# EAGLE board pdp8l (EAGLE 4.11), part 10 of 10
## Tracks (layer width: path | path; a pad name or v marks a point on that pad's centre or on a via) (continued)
VCC  (via drill 0.61) (continued)
  Bottom 0.508: 358.44,271.73 349.1,271.73 348.29,272.54 A09.A2 347.07,272.95 345.85,272.95 344.22,274.57 336.91,274.57 335.69,273.36 A10.A2 334.47,272.54 333.65,271.73 323.49,271.73 322.68,272.54 A11.A2 321.46,272.95 320.65,272.14 317.4,272.14 316.99,271.73 307.64,271.73 | 358.44,271.73 359.66,272.95 A08.A2 | 358.44,271.73 371.04,271.73 372.26,272.95 AB07.AA2 373.48,273.76 374.29,274.57 387.71,274.57 | 387.71,274.57 386.49,273.36 AB06.AA2 | 387.71,274.57 396.65,274.57 | 396.65,274.57 397.87,273.36 AB05.AA2 | 409.25,274.57 410.46,273.36 AB04.AA2 | 396.65,274.57 409.25,274.57 | 421.84,274.57 423.06,273.36 AB03.AA2 | 409.25,274.57 421.84,274.57 | 434.85,274.57 436.07,273.36 AB02.AA2 | 421.84,274.57 434.85,274.57 | 434.85,274.57 447.45,274.57 448.67,273.36 A01.A2 | 15.44,271.73 6.1,271.73 5.28,272.54 A36.A2 | 15.44,271.73 16.66,272.95 A35.A2 | 28.85,271.73 29.67,272.54 A34.A2 | 28.85,271.73 15.44,271.73 | 28.85,271.73 41.45,271.73 42.27,272.54 A33.A2 | A32.A2 56.08,272.54 56.9,271.73 66.24,271.73 67.46,272.95 AB31.AA2 68.68,272.54 69.09,272.14 73.15,272.14 73.56,271.73 75.59,271.73 76.4,272.54 80.47,272.54 AB30.AA2 81.69,272.95 82.5,272.14 86.16,272.14 86.56,271.73 92.25,271.73 93.07,272.54 AB29.AA2 94.28,272.95 97.94,272.95 99.16,271.73 100.79,271.73 101.6,272.54 105.26,272.54 105.66,272.95 A28A.A2 | A24.A2 157.68,272.54 161.75,272.54 162.56,271.73 165.81,271.73 167.03,272.95 169.06,272.95 A23.A2 170.28,273.76 171.09,274.57 209.7,274.57 | 209.7,274.57 208.48,273.36 A20.A2 | 209.7,274.57 218.64,274.57 219.86,273.36 A19.A2 221.08,272.54 221.49,272.14 225.55,272.14 225.96,271.73 231.24,271.73 232.05,272.54 232.87,272.54 A18.A2 234.09,273.36 235.31,274.57 244.25,274.57 245.47,273.36 A17.A2 246.69,272.54 247.5,271.73 256.85,271.73
  Bottom 0.508: 256.85,271.73 258.06,272.95 A16.A2 | 269.44,271.73 270.66,272.95 A15.A2 | 256.85,271.73 269.44,271.73 | 282.85,271.73 283.67,272.54 A14.A2 | 269.44,271.73 282.85,271.73 | 295.45,271.73 296.27,272.54 A13.A2 | 282.85,271.73 295.45,271.73 | 307.64,271.73 308.86,272.95 A12.A2 | 295.45,271.73 307.64,271.73 | D01.A2 448.67,66.5 447.45,65.28 442.16,65.28 440.94,66.5 437.29,66.5 D02.A2 436.07,66.09 435.25,65.28 425.09,65.28 424.28,66.09 CD03.BA2 423.06,66.5 419.81,66.5 418.59,65.28 413.71,65.28 412.5,66.5 411.68,66.5 D04.A2 410.46,66.5 406.81,66.5 405.59,65.28 400.3,65.28 399.08,66.5 D05.A2 397.87,66.9 396.24,66.9 395.02,68.12 387.71,68.12 386.49,66.9 D06.A2 385.27,66.09 382.02,66.09 381.2,65.28 378.36,65.28 377.95,65.68 373.89,65.68 373.48,66.09 D07.A2 372.26,66.5 369.82,66.5 368.61,65.28 365.76,65.28 365.35,65.68 361.29,65.68 360.88,66.09 D08.A2 359.66,66.5 358.85,65.68 355.19,65.68 354.79,65.28 352.75,65.28 351.54,66.5 348.29,66.5 D09.A2 347.07,66.5 345.85,65.28 336.91,65.28 335.69,66.5 D10.A2 334.47,66.09 334.06,65.68 330,65.68 329.59,65.28 320.24,65.28 | 53.65,68.12 44.7,68.12 43.48,66.9 D33.A2 | 53.65,68.12 54.86,66.9 D32.A2 | 66.24,68.12 67.46,66.9 D31.A2 | 66.24,68.12 53.65,68.12 | 79.65,68.12 80.47,67.31 D30.A2 | 79.65,68.12 66.24,68.12 | 89,67.31 88.19,68.12 79.65,68.12 | 89,67.31 89.41,66.9 93.07,66.9 D29.A2 | 99.57,69.34 102.41,66.5 105.66,66.5 D28.A2 | 99.57,69.34 91.03,69.34 89,67.31 | 99.57,69.34 v115.82,69.34 116.23,69.34 v145.09,69.34 | 155.25,65.28 149.96,65.28 149.15,66.09 145.49,66.09 145.09,66.5 D25.A2 | 155.25,65.28 156.46,66.5 D24.A2
  Bottom 0.508: 155.25,65.28 167.84,65.28 169.06,66.5 D23.A2 170.28,67.31 171.09,68.12 217.83,68.12 219.05,66.9 219.86,66.9 D19.A2 221.08,67.31 221.89,68.12 232.05,68.12 232.87,67.31 D18.A2 234.09,66.5 234.49,66.09 238.15,66.09 238.96,65.28 240.59,65.28 241.81,66.5 245.47,66.5 D17.A2 246.69,66.5 247.5,65.68 251.16,65.68 251.56,65.28 256.85,65.28 | 256.85,65.28 258.06,66.5 D16.A2 | 269.44,65.28 270.66,66.5 D15.A2 | 256.85,65.28 269.44,65.28 | 282.85,65.28 283.67,66.09 D14.A2 | 269.44,65.28 282.85,65.28 | 295.05,65.28 296.27,66.5 D13.A2 | 282.85,65.28 295.05,65.28 | 307.64,65.28 308.86,66.5 D12.A2 | 295.05,65.28 307.64,65.28 | 320.24,65.28 321.46,66.5 D11.A2 | 307.64,65.28 320.24,65.28 | 53.65,135.18 44.3,135.18 43.48,135.99 C33.A2 | 53.65,135.18 54.86,136.4 C32.A2 | 66.24,135.18 67.46,136.4 C31.A2 | 53.65,135.18 66.24,135.18 | 79.65,135.18 80.47,135.99 C30.A2 | 66.24,135.18 79.65,135.18 | 92.25,135.18 93.07,135.99 C29.A2 | 79.65,135.18 92.25,135.18 | 92.25,135.18 104.44,135.18 105.66,136.4 C28.A2 106.88,136.8 108.1,138.02 117.04,138.02 | 117.04,138.02 118.26,136.8 C27.A2 | 130.05,138.02 131.27,136.8 C26.A2 | 117.04,138.02 130.05,138.02 | 142.65,138.02 143.87,136.8 C25.A2 | 130.05,138.02 142.65,138.02 | 155.25,138.02 156.46,136.8 C24.A2 | 142.65,138.02 155.25,138.02 | 155.25,138.02 167.84,138.02 169.06,136.8 C23.A2 170.28,137.21 171.09,138.02 221.89,138.02 | 221.89,138.02 222.3,138.43 231.24,138.43 232.87,136.8 C18.A2 234.09,136.8 235.31,138.02 244.25,138.02 245.47,136.8 C17.A2 246.69,135.99 247.5,135.18 256.85,135.18 258.06,136.4 C16.A2 259.28,135.99 260.1,135.18 269.44,135.18 270.66,136.4 C15.A2 271.88,135.99 272.69,135.18 278.79,135.18 279.2,135.59 283.26,135.59 283.67,135.99 C14.A2 284.89,136.4 285.7,135.59 289.36,135.59 289.76,135.18 291.39,135.18 292.61,136.4 296.27,136.4 C13.A2 297.49,135.99 298.3,135.18 303.99,135.18 305.21,136.4 308.86,136.4 C12.A2 310.08,135.99 310.49,135.59 314.55,135.59 314.96,135.18 316.99,135.18 318.21,136.4 321.46,136.4 C11.A2 322.68,135.99 323.49,135.18 333.65,135.18 334.47,135.99 C10.A2 335.69,136.4 337.31,136.4 338.53,135.18 342.19,135.18 342.6,135.59 346.66,135.59 347.07,135.99 C09.A2 348.29,135.99 348.69,135.59 352.75,135.59 353.16,135.18 356.01,135.18 357.23,136.4 359.66,136.4 C08.A2 360.88,135.99 361.29,135.59 365.35,135.59 365.76,135.18 368.2,135.18 369.42,136.4 372.26,136.4 C07.A2 373.48,135.99 374.29,135.18 387.71,135.18
  Bottom 0.508: 221.89,138.02 221.08,137.21 C19.A2 | 435.25,135.18 425.09,135.18 424.28,135.99 CD03.AA2 423.06,136.4 419.81,136.4 418.19,138.02 412.9,138.02 411.68,136.8 C04.A2 410.46,136.4 409.25,135.18 397.05,135.18 | 435.25,135.18 436.07,135.99 C02.A2 | 435.25,135.18 447.85,135.18 448.67,135.99 C01.A2 | 387.71,135.18 386.49,136.4 C06.A2 | 387.71,135.18 397.05,135.18 | 397.05,135.18 397.87,135.99 C05.A2 | 295.45,201.83 286.11,201.83 284.89,203.05 B14.A2 283.67,202.64 279.6,202.64 278.79,201.83 269.44,201.83 | 295.45,201.83 296.27,202.64 B13.A2 | 307.64,201.83 308.86,203.05 B12.A2 | 307.64,201.83 295.45,201.83 | 320.24,201.83 321.46,203.05 B11.A2 | 320.24,201.83 307.64,201.83 | 332.44,201.83 320.24,201.83 | 332.44,201.83 333.65,201.83 334.47,202.64 B10.A2 335.69,203.05 338.12,203.05 339.34,201.83 346.25,201.83 347.07,202.64 B09.A2 348.29,203.05 349.5,201.83 355.19,201.83 356.01,202.64 360.07,202.64 B08.A2 360.88,203.45 362.1,204.67 371.04,204.67 372.26,203.45 AB07.BA2 373.48,202.64 374.29,201.83 387.71,201.83 | 387.71,201.83 386.49,203.05 AB06.BA2 | 387.71,201.83 392.99,201.83 393.8,202.64 397.87,202.64 AB05.BA2 399.08,203.05 399.9,202.23 403.56,202.23 403.96,201.83 412.5,201.83 | 412.5,201.83 411.68,202.64 AB04.BA2 | 412.5,201.83 421.84,201.83 | 421.84,201.83 423.06,203.05 AB03.BA2 | 435.25,201.83 436.07,202.64 AB02.BA2 | 421.84,201.83 435.25,201.83 | 435.25,201.83 447.85,201.83 448.67,202.64 B01.A2 | B33.A2 43.48,203.05 44.7,201.83 53.65,201.83 54.86,203.05 B32.A2 56.08,202.64 56.9,201.83 66.24,201.83 | 66.24,201.83 67.46,203.05 AB31.BA2 | 66.24,201.83 79.65,201.83 80.47,202.64 AB30.BA2 81.69,203.45 84.94,203.45 86.16,204.67 91.85,204.67 93.07,203.45 AB29.BA2 94.28,203.45 95.5,204.67 104.44,204.67 105.66,203.45 B28.A2 106.88,203.45 108.1,204.67 155.25,204.67 156.46,203.45 B24.A2 157.68,202.64 158.5,201.83 167.84,201.83 169.06,203.05 B23.A2 170.28,203.86 171.09,204.67 209.7,204.67
  Bottom 0.508: 209.7,204.67 208.48,203.45 B20.A2 | 218.64,204.67 209.7,204.67 | 218.64,204.67 219.86,203.45 B19.A2 | 218.64,204.67 232.05,204.67 232.87,203.86 B18.A2 234.09,203.05 235.31,201.83 244.65,201.83 | 244.65,201.83 245.47,202.64 B17.A2 | 256.85,201.83 258.06,203.05 B16.A2 | 256.85,201.83 244.65,201.83 | 269.44,201.83 270.66,203.05 B15.A2 | 269.44,201.83 256.85,201.83 | v332.44,203.05 332.44,201.83
WC_OVERFLOW\  (via drill 0.61)
  Route2 0.203: v304.39,14.07 334.47,44.15 334.47,46.99 D10.H2
  Route15 0.203: v209.7,8.79 209.7,22.61 164.19,68.12 160.53,68.12 156.06,72.59 156.06,76.25 123.14,109.17 120.7,109.17 119.48,110.39 C27.K2
  Bottom 0.203: v304.39,14.07 301.14,10.82 232.05,10.82 230.02,8.79 v209.7,8.79
WC_SET\  (via drill 0.61)
  Top 0.203: 308.05,20.98 308.86,21.79 D12.S2 | 307.64,20.57 308.05,20.98 | 307.64,20.57 306.83,19.76 D12.T2 | v145.09,6.76 130.05,21.79 130.05,87.63 129.24,88.44 C26.T2 | v305.61,9.6 307.64,11.63 307.64,20.57 | 308.05,20.98 308.05,33.17 309.27,34.39 D12.M2
  Bottom 0.203: v145.09,6.76 145.49,6.35 181.66,6.35 182.07,5.94 212.14,5.94 212.55,6.35 245.87,6.35 246.69,7.16 261.31,7.16 262.94,5.54 291.39,5.54 292.61,6.76 302.77,6.76 v305.61,9.6 | D11.M2 321.46,34.8 320.24,33.58 310.9,33.58 310.08,34.39 D12.M2
WORD_COUNT
  Bottom 0.203: D10.P2 335.69,28.3 340.56,28.3 D10.P1
WORD_COUNT\  (via drill 0.61)
  Top 0.203: v421.84,40.89 421.84,28.3 417.78,24.23 417.78,23.01 D04.S1 | D11.H1 328.78,46.99 330,45.77 330,34.39 329.59,33.98 329.59,32.36 330.4,31.55 330.4,26.67 331.22,25.86 D10.R2 332.03,24.64 333.25,23.42 333.25,12.04 332.44,11.23 327.15,11.23 327.15,14.07 317.4,23.83 | 310.9,16.51 314.55,16.51 314.55,18.95 317.4,21.79 317.4,23.83 | 310.9,16.51 310.08,16.51 D12.U2 | 317.4,23.83 317.4,33.17 316.18,34.39 D12.M1 | v134.11,77.47 130.45,81.13 130.45,118.92 129.24,120.14 C26.F2 | v304.8,70.16 304.8,43.33 310.9,37.24 310.9,16.51 | v305.61,230.28 304.8,229.46 304.8,207.92 305.61,207.11 305.61,201.42 305.21,201.02 v305.21,189.23 | v298.3,189.23 v298.3,146.96 | v288.14,146.96 288.14,134.77 288.54,134.37 v288.54,75.84
  Bottom 0.203: D02.S2 436.07,21.79 435.25,20.98 419,20.98 418.19,21.79 D04.S1 416.97,22.61 416.15,23.42 341.78,23.42 338.53,26.67 333.25,26.67 332.44,25.86 D10.R2 | v421.84,40.89 423.47,42.52 434.04,42.52 434.44,42.93 444.19,42.93 445.41,44.15 D01.J2 | v134.11,77.47 141.43,70.16 176.78,70.16 177.19,69.75 288.54,69.75 288.95,70.16 | 288.95,70.16 v304.8,70.16 | v305.61,230.28 317.81,230.28 318.62,231.09 A11.R2 | v305.21,189.23 v298.3,189.23 | v298.3,146.96 v288.14,146.96 | v288.54,75.84 288.54,70.16 288.95,70.16
WRITE  (via drill 0.61)
  Top 0.203: C25.L1 147.52,108.76 146.3,109.98 146.3,125.02 147.52,126.24 C25.D1 | 143.05,36.83 144.27,35.61 D25.M2 | 143.05,36.83 v143.05,55.52 | v260.1,14.88 260.1,20.98 259.28,21.79 D16.S2 | v141.83,14.48 143.05,15.7 143.05,27.89 | 143.05,27.89 143.05,36.83 | v138.99,109.58 136.96,107.54 136.96,33.98 143.05,27.89
  Bottom 0.203: D16.S2 259.28,21.79 264.57,21.79 D16.S1 | v143.05,55.52 141.83,56.74 D25.D2 | v260.1,14.88 259.69,14.48 v141.83,14.48 | v138.99,109.58 145.9,109.58 147.12,108.36 C25.L1
X_R/W_RETURN  (via drill 0.61)
  Top 0.203: v152.4,165.66 152.81,165.25 152.81,52.68 v153.21,52.27 152.81,52.27 152.81,49.84 155.65,46.99 155.65,21.79 v158.09,19.36 | v149.56,50.24 149.56,42.52 150.37,41.71 D25.K1
  Route15 0.203: v152.4,165.66 128.83,189.23 128.83,192.89 B26.D2
  Bottom 0.203: D18.T2 229.62,18.54 228.8,17.73 219.46,17.73 218.24,18.95 D19.T2 217.02,18.54 216.21,17.73 159.72,17.73 v158.09,19.36 | 149.56,52.27 143.05,52.27 141.83,51.05 D25.F2 | v153.21,52.27 149.56,52.27 | 149.56,52.27 v149.56,50.24
X_R/W_SOURCE  (via drill 0.61)
  Top 0.203: v150.77,115.67 150.77,111.61 C25.K1 | A26.D2 129.24,263.2 133.71,263.2 133.71,203.45 136.14,201.02 136.14,128.27 141.02,123.39 141.02,121.36 C25.F2 | v155.65,110.39 155.25,109.98 155.25,90.88 154.03,89.66 C24.T2
  Bottom 0.203: C24.T2 154.43,88.44 154.84,88.04 159.31,88.04 159.72,87.63 163.78,87.63 164.59,88.44 166.22,88.44 C23.T2 | v150.77,115.67 141.83,115.67 141.83,120.14 C25.F2 | v155.65,110.39 155.25,110.79 151.59,110.79 C25.K1
Y_R/W_RETURN
  Top 0.203: A25.D2 141.43,262.79 143.05,261.16 143.05,239.22 149.56,232.72 149.56,158.34 152.4,155.5 152.4,24.23 151.18,23.01 D25.S1 151.18,21.79 151.18,21.39 153.21,19.36 D24.T2
  Bottom 0.203: D25.P2 144.68,27.89 144.68,23.42 149.56,23.42 150.37,22.61 D25.S1 | D23.T2 166.22,19.36 165,20.57 155.25,20.57 154.43,19.76 D24.T2
Y_R/W_SOURCE  (via drill 0.61)
  Top 0.203: v148.74,190.45 149.15,190.04 149.15,105.1 144.68,100.63 144.68,99.01 C25.P2 | v212.55,92.1 212.55,89.26 217.02,89.26 C19.T2
  Bottom 0.203: C19.T2 218.24,89.26 219.05,90.07 228.8,90.07 229.62,89.26 C18.T2 | v148.74,190.45 149.96,191.67 151.18,191.67 151.18,192.89 149.15,194.92 142.65,194.92 141.83,194.11 B25.D2 | C25.P2 145.09,98.2 146.3,96.98 150.37,96.98 150.37,92.51 C25.S1 151.59,91.69 152.4,90.88 211.33,90.88 v212.55,92.1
